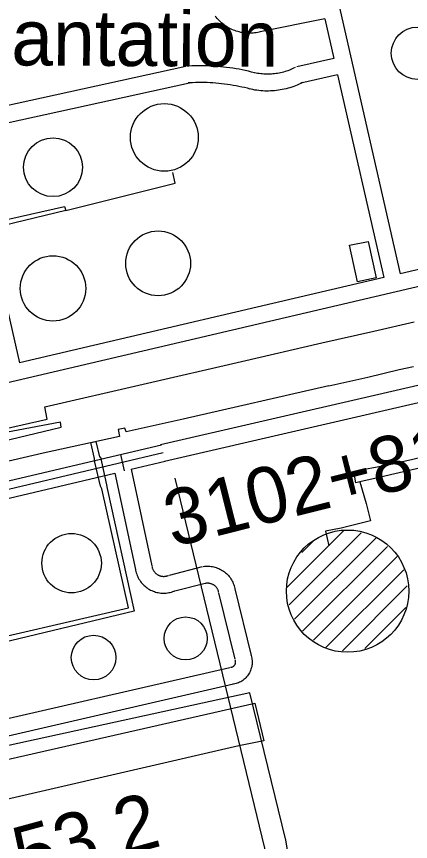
# Model space of a CAD drawing. Extents: x 3392644 to 3430565, y 576657 to 602123.
# Drawn here: x 3415681 to 3416383, y 584566 to 586038 of the extents above; entities that cross this region are included whole.
import ezdxf

# ---------------------------------------------------------------- set-up
doc = ezdxf.new("R2010")
doc.units = 0
for name, color, linetype in [('V-BLDG-IDEN', 7, 'Continuous'), ('V-BLDG-OTLN', 7, 'Continuous'), ('V-DOMW-TANK', 7, 'Continuous'), ('V-ROAD-CNTR', 7, 'Continuous'), ('V-SITE-OTLN', 7, 'Continuous'), ('V-SURV-IDEN', 7, 'Continuous'), ('V-TOPO-SHOR', 7, 'Continuous'), ('V-UTIL-LINE', 7, 'Continuous')]:
    doc.layers.add(name, color=color, linetype=linetype)

msp = doc.modelspace()

# ---------------------------------------------------------------- linework, layer by layer
at = {"layer": 'V-BLDG-OTLN'}
msp.add_lwpolyline([(3416308.1, 585636.6), (3416322, 585571.5), (3416288.7, 585564.4), (3416274.7, 585629.8)], close=True, dxfattribs=at)
at = {"layer": 'V-DOMW-TANK'}
for p, q in [((3416162.4, 585018.6), (3416264.3, 585120.5)), ((3416167.3, 584988.1), (3416295.7, 585116.5)), ((3416176.8, 584962.3), (3416322.9, 585108.3)), ((3416189.7, 585081.3), (3416210, 585101.5)), ((3416190.9, 584941), (3416342.2, 585092.3)), ((3416210.3, 584925), (3416359.8, 585074.5)), ((3416232.1, 584911.5), (3416371.3, 585050.7)), ((3416262.3, 584906.3), (3416377.7, 585021.8)), ((3416301.8, 584910.5), (3416374.9, 584983.6))]:
    msp.add_line(p, q, dxfattribs=at)
for centre, radius in [((3416395.9, 585972.7), 46.7), ((3415944.6, 585822.3), 60.4), ((3415746.2, 585769.1), 52.4), ((3415933.5, 585597.6), 57.8), ((3415746.1, 585552.9), 58.3), ((3416271.3, 585012.6), 109.1), ((3415779.3, 585062.5), 53), ((3415982.6, 584928.2), 38.4), ((3415818.5, 584894.1), 39.8)]:
    msp.add_circle(centre, radius, dxfattribs=at)
at = {"layer": 'V-ROAD-CNTR'}
msp.add_line((3415866.2, 585256.5), (3415873.1, 585227.3), dxfattribs=at)
for points in [[(3416145.1, 586545.8), (3416364.9, 585579.2)], [(3416116.1, 586010.9), (3416113.7, 586010.3), (3416111, 586009.8), (3416108.3, 586009.3), (3416105.6, 586008.9), (3416102.8, 586008.6), (3416100.1, 586008.4), (3416097.3, 586008.4), (3416094.6, 586008.4), (3416091.8, 586008.5), (3416089.1, 586008.7), (3416086.3, 586009), (3416083.6, 586009.4), (3416080.9, 586009.9), (3416078.2, 586010.6), (3416075.6, 586011.3), (3416072.9, 586012.1), (3416070.3, 586013), (3416067.8, 586014), (3416065.2, 586015), (3416062.7, 586016.2), (3416060.3, 586017.5), (3416057.9, 586018.8), (3416055.5, 586020.3), (3416053.3, 586021.8), (3416051, 586023.4), (3416048.8, 586025.1), (3416046.7, 586026.8), (3416044.7, 586028.7), (3416042.7, 586030.6), (3416040.8, 586032.6), (3416038.9, 586034.6), (3416037.2, 586036.7), (3416035.5, 586038.9)], [(3416230.7, 586034), (3416115.4, 586010.8)], [(3416230.7, 586034), (3416246.8, 585963.2)], [(3416246.8, 585963.2), (3416181, 585948.3)], [(3415448.7, 585832.1), (3415983.1, 585949.3)], [(3416105.3, 585937.7), (3416099.9, 585939.1), (3416094.4, 585940.4), (3416089, 585941.6), (3416083.4, 585942.8), (3416077.9, 585943.9), (3416072.4, 585944.8), (3416066.8, 585945.8), (3416061.2, 585946.6), (3416055.7, 585947.3), (3416050.1, 585948), (3416044.5, 585948.6), (3416038.9, 585949.1), (3416033.2, 585949.5), (3416027.6, 585949.8), (3416022, 585950), (3416016.4, 585950.2), (3416010.7, 585950.3), (3416005.1, 585950.3), (3415999.5, 585950.2), (3415993.8, 585950), (3415988.2, 585949.8), (3415985.5, 585949.6)], [(3416177.7, 585947.1), (3416175.1, 585945.8), (3416172.6, 585944.6), (3416170.1, 585943.5), (3416167.5, 585942.5), (3416165, 585941.5), (3416162.4, 585940.6), (3416159.8, 585939.8), (3416157.1, 585939), (3416154.5, 585938.3), (3416151.8, 585937.7), (3416149.1, 585937.1), (3416146.4, 585936.7), (3416143.7, 585936.2), (3416141, 585935.9), (3416138.3, 585935.6), (3416135.5, 585935.4), (3416132.8, 585935.2), (3416130.1, 585935.2), (3416127.3, 585935.2), (3416124.6, 585935.2), (3416121.8, 585935.4), (3416119.1, 585935.6), (3416116.4, 585935.8), (3416113.7, 585936.2), (3416110.9, 585936.6), (3416108.2, 585937.1), (3416105.5, 585937.7), (3416104.8, 585937.8)], [(3416253.5, 585934), (3416187.7, 585919)], [(3416253.5, 585934), (3416335.7, 585572.4)], [(3415455.2, 585802.8), (3415989.5, 585920)], [(3416097.8, 585908.6), (3416092.7, 585910), (3416087.6, 585911.2), (3416082.6, 585912.3), (3416077.5, 585913.4), (3416072.4, 585914.4), (3416067.3, 585915.3), (3416062.2, 585916.1), (3416057.1, 585916.9), (3416051.9, 585917.6), (3416046.8, 585918.2), (3416041.6, 585918.7), (3416036.4, 585919.2), (3416031.3, 585919.5), (3416026.1, 585919.8), (3416020.9, 585920.1), (3416015.7, 585920.2), (3416010.5, 585920.3), (3416005.3, 585920.3), (3416000.2, 585920.2), (3415995, 585920), (3415989.8, 585919.8), (3415987.1, 585919.7)], [(3416191.1, 585920.2), (3416188.1, 585918.7), (3416184.9, 585917.3), (3416181.7, 585915.9), (3416178.4, 585914.5), (3416175.2, 585913.3), (3416171.8, 585912.2), (3416168.5, 585911.1), (3416165.1, 585910.1), (3416161.7, 585909.2), (3416158.3, 585908.4), (3416154.9, 585907.7), (3416151.4, 585907.1), (3416148, 585906.5), (3416144.5, 585906.1), (3416141, 585905.7), (3416137.5, 585905.4), (3416134, 585905.3), (3416130.5, 585905.2), (3416127, 585905.2), (3416123.5, 585905.2), (3416120, 585905.4), (3416116.5, 585905.7), (3416113, 585906), (3416109.5, 585906.5), (3416106, 585907), (3416102.6, 585907.6), (3416099.2, 585908.3), (3416098.3, 585908.5)], [(3417410.7, 585793.4), (3415040.3, 585238.2)], [(3416857.5, 585694.6), (3416364.9, 585579.2)], [(3417653.5, 585639.1), (3415944.7, 585244.2)], [(3417448.6, 585622.5), (3415938, 585273.5)], [(3415643.6, 585606.2), (3415686.3, 585420.3)], [(3416335.7, 585572.4), (3415686.3, 585420.3)], [(3414841.6, 585028.8), (3415009.8, 585064.2), (3415617.8, 585197.9), (3415939.4, 585273.8)], [(3415942.8, 585259.2), (3415621.1, 585183.3), (3415013, 585049.5), (3414844.7, 585014.1)], [(3415885.4, 585230.2), (3415946.2, 585244.6)], [(3415483.8, 585137.7), (3415624.5, 585168.7), (3415856.2, 585223.3)], [(3415856.2, 585223.3), (3415893.1, 585051.3)], [(3415885.3, 585230.5), (3415885.6, 585229.3)], [(3415885.4, 585230.2), (3415922.4, 585057.6)], [(3415893, 585051.8), (3415893.4, 585049.8), (3415893.9, 585047.4), (3415894.5, 585045.1), (3415895.3, 585042.8), (3415896.2, 585040.6), (3415897.1, 585038.4), (3415898.2, 585036.2), (3415899.4, 585034.1), (3415900.7, 585032.1), (3415902, 585030.1), (3415903.5, 585028.2), (3415905, 585026.4), (3415906.6, 585024.6), (3415908.4, 585022.9), (3415910.2, 585021.3), (3415912, 585019.8), (3415913.9, 585018.3), (3415915.9, 585017), (3415918, 585015.7), (3415920.1, 585014.6), (3415922.3, 585013.5), (3415924.5, 585012.6), (3415926.8, 585011.8), (3415929, 585011), (3415931.4, 585010.4), (3415933.7, 585009.9), (3415936.1, 585009.5), (3415938.5, 585009.2), (3415940.9, 585009), (3415943.3, 585009), (3415945.7, 585009), (3415948.1, 585009.2), (3415950.5, 585009.5), (3415952.9, 585009.9), (3415955.2, 585010.3), (3415957.5, 585011), (3415959.8, 585011.7), (3415962, 585012.5), (3415963.1, 585012.9)], [(3415922.5, 585057.2), (3415922.7, 585055.8), (3415923, 585054.9), (3415923.2, 585053.9), (3415923.5, 585053), (3415923.9, 585052), (3415924.3, 585051.1), (3415924.7, 585050.2), (3415925.2, 585049.4), (3415925.8, 585048.5), (3415926.3, 585047.7), (3415926.9, 585046.9), (3415927.6, 585046.2), (3415928.2, 585045.4), (3415928.9, 585044.7), (3415929.7, 585044.1), (3415930.5, 585043.4), (3415931.3, 585042.8), (3415932.1, 585042.3), (3415932.9, 585041.8), (3415933.8, 585041.3), (3415934.7, 585040.9), (3415935.6, 585040.5), (3415936.5, 585040.1), (3415937.5, 585039.8), (3415938.4, 585039.6), (3415939.4, 585039.4), (3415940.4, 585039.2), (3415941.4, 585039.1), (3415942.4, 585039), (3415943.4, 585039), (3415944.4, 585039), (3415945.4, 585039.1), (3415946.3, 585039.2), (3415947.3, 585039.3), (3415948.3, 585039.6), (3415949.3, 585039.8), (3415950.2, 585040.1), (3415951.2, 585040.5), (3415951.8, 585040.7)], [(3415953.8, 585041.4), (3416012.4, 585056.3)], [(3416014, 585056.6), (3416016.1, 585056.9), (3416018.4, 585057.1), (3416020.8, 585057.2), (3416023.2, 585057.2), (3416025.6, 585057.1), (3416027.9, 585056.8), (3416030.3, 585056.5), (3416032.6, 585056), (3416034.9, 585055.4), (3416037.2, 585054.7), (3416039.5, 585053.9), (3416041.7, 585053), (3416043.8, 585052), (3416045.9, 585050.9), (3416048, 585049.6), (3416050, 585048.3), (3416051.9, 585046.9), (3416053.8, 585045.4), (3416055.5, 585043.8), (3416057.2, 585042.2), (3416058.8, 585040.4), (3416060.4, 585038.6), (3416061.8, 585036.7), (3416063.2, 585034.7), (3416064.4, 585032.7), (3416065.6, 585030.6), (3416066.6, 585028.4), (3416067.6, 585026.3), (3416068.4, 585024), (3416069.1, 585021.8), (3416069.8, 585019.5), (3416070.3, 585017.2), (3416070.5, 585015.9)], [(3415961.2, 585012.3), (3416019.8, 585027.2)], [(3416018.1, 585026.9), (3416019.4, 585027.1), (3416020.4, 585027.2), (3416021.3, 585027.2), (3416022.3, 585027.2), (3416023.2, 585027.2), (3416024.1, 585027.1), (3416025, 585026.9), (3416026, 585026.7), (3416026.9, 585026.5), (3416027.8, 585026.2), (3416028.7, 585025.9), (3416029.5, 585025.5), (3416030.4, 585025.1), (3416031.2, 585024.7), (3416032, 585024.2), (3416032.8, 585023.7), (3416033.6, 585023.1), (3416034.3, 585022.6), (3416035, 585021.9), (3416035.7, 585021.3), (3416036.3, 585020.6), (3416036.9, 585019.9), (3416037.5, 585019.1), (3416038, 585018.3), (3416038.5, 585017.5), (3416039, 585016.7), (3416039.4, 585015.9), (3416039.8, 585015), (3416040.1, 585014.1), (3416040.4, 585013.2), (3416040.6, 585012.3), (3416040.8, 585011.3), (3416041, 585010.6)], [(3416070.3, 585016.8), (3416099.2, 584898)], [(3416041.2, 585009.7), (3416070, 584890.9)], [(3416098.8, 584899.2), (3416099.4, 584897.5), (3416100, 584895.3), (3416100.5, 584893.1), (3416100.8, 584890.9), (3416101.1, 584888.6), (3416101.2, 584886.4), (3416101.1, 584884.1), (3416101, 584881.9), (3416100.7, 584879.6), (3416100.3, 584877.4), (3416099.7, 584875.2), (3416099.1, 584873.1), (3416098.3, 584870.9), (3416097.4, 584868.9), (3416096.4, 584866.8), (3416095.2, 584864.9), (3416094, 584863), (3416092.7, 584861.2), (3416091.2, 584859.4), (3416089.7, 584857.8), (3416088, 584856.2), (3416086.3, 584854.8), (3416084.5, 584853.4), (3416082.6, 584852.1), (3416080.7, 584851), (3416078.7, 584850), (3416076.6, 584849), (3416074.5, 584848.2), (3416072.4, 584847.5), (3416070.2, 584847), (3416068, 584846.6), (3416066.8, 584846.4)], [(3416070.4, 584889.6), (3416070.7, 584888.6), (3416070.9, 584888.1), (3416071, 584887.6), (3416071.1, 584887), (3416071.1, 584886.5), (3416071.2, 584885.9), (3416071.1, 584885.4), (3416071.1, 584884.8), (3416071, 584884.3), (3416070.9, 584883.7), (3416070.8, 584883.2), (3416070.6, 584882.6), (3416070.5, 584882.1), (3416070.2, 584881.6), (3416070, 584881.1), (3416069.7, 584880.6), (3416069.4, 584880.2), (3416069.1, 584879.7), (3416068.7, 584879.3), (3416068.3, 584878.9), (3416067.9, 584878.5), (3416067.5, 584878.2), (3416067.1, 584877.8), (3416066.6, 584877.5), (3416066.1, 584877.2), (3416065.6, 584877), (3416065.1, 584876.8), (3416064.6, 584876.6), (3416064.1, 584876.4), (3416063.6, 584876.3), (3416062.9, 584876.1), (3416062.4, 584876.1)], [(3416061.2, 584875.8), (3415574.2, 584763.6)], [(3416068, 584846.6), (3415580.9, 584734.4)]]:
    msp.add_lwpolyline(points, dxfattribs=at)
at = {"layer": 'V-SITE-OTLN'}
msp.add_lwpolyline([(3416164.3, 584550.7), (3416161.1, 584568), (3416097, 584831.4), (3415528, 584706.7), (3415441.1, 585124.8), (3414885.8, 585003.9), (3414787.6, 585534.1), (3414674, 586142.1), (3414579.1, 586564.1), (3414488.4, 587013.5), (3414833, 587097.6), (3414846.4, 587100.5), (3414856, 587102.4), (3414865.5, 587103.9), (3415026.6, 587138), (3415544.3, 587252.4), (3415572.5, 587260.1), (3415594.5, 587264.5), (3415667.1, 587280.6), (3416201.5, 587400.8), (3417016.1, 587577.2)], dxfattribs=at)
at = {"layer": 'V-TOPO-SHOR'}
msp.add_lwpolyline([(3415085.2, 584609.3), (3415094.3, 584582.4), (3416106.1, 584812.9), (3416122.1, 584745.6), (3416077.2, 584736.4), (3415168.6, 584526.6), (3415139.4, 584535.4), (3414977.9, 584496.7), (3414971, 584532.6), (3414973.2, 584552.8), (3414975.4, 584573), (3414977.6, 584575.3)], dxfattribs=at)
at = {"layer": 'V-UTIL-LINE'}
for points in [[(3414748.9, 586207.2), (3414831.3, 585765), (3414934.3, 585199.3), (3414951, 585115), (3415354.5, 585207.7), (3415760.9, 585305.2), (3415759.7, 585314.1), (3415652.8, 585293.8), (3415634.4, 585364.5), (3415644.7, 585367.7), (3415659.8, 585302.5), (3415735.9, 585319.4), (3415731.5, 585341.4), (3416082.4, 585422.3), (3416225.2, 585455.5)], [(3415769, 585691.9), (3415964, 585740.7), (3415959.8, 585759.9)], [(3415644.7, 585671.7), (3415766.4, 585699.3), (3415769, 585691.9), (3415658.2, 585665.1)], [(3416225.2, 585455.5), (3416318.1, 585476.6), (3416390, 585493.1)], [(3416427.5, 585238.6), (3416322, 585214.4), (3416293, 585207.5), (3416286.2, 585205.9), (3416282.6, 585226.6), (3416339.8, 585237.3), (3416387.4, 585248), (3416421.1, 585256.5), (3416418.3, 585265.5), (3416468.6, 585276.1), (3416550.7, 585293.3), (3416567.9, 585296.8), (3416564.4, 585307.2), (3416629.2, 585323.5), (3416741.5, 585349.8), (3416796, 585362.5), (3416883.5, 585383.1), (3416984.2, 585403.8), (3417053.9, 585416), (3417144.2, 585433.2), (3417204.8, 585447.4), (3417229, 585453.8), (3417231.8, 585443.5)], [(3416238, 585378.8), (3416307.3, 585394.7), (3416363.5, 585408.2), (3416388.5, 585413.7)], [(3416238, 585378.8), (3415977.9, 585319.3), (3415876.3, 585296.8), (3415874.4, 585303.7), (3415862.1, 585301.2), (3415864.5, 585288.8), (3415728.7, 585258.9), (3415432.9, 585189.8), (3414940.8, 585077.8), (3414887.3, 585065.2)], [(3415822.5, 585279.6), (3415829.1, 585252.5), (3415830.9, 585251.6), (3415841.7, 585202.2), (3415842.5, 585195.8), (3415890.8, 584977.1), (3415570.4, 584899.9), (3415567, 584910), (3415880.9, 584982.8), (3415833.4, 585195.1), (3415830.8, 585199.7), (3415820.7, 585242.7), (3415819.9, 585249.1), (3415813.4, 585277.6), (3415822.5, 585279.6)], [(3412089.9, 582100), (3412531, 582457.8), (3414603.6, 584199.2), (3415068.6, 584289.5), (3415163.5, 584253.5), (3416142.9, 584475.3), (3415963.7, 585214)], [(3416293, 585207.5), (3416304.2, 585168.9), (3416312.1, 585137.9), (3416259.7, 585125.1), (3416232.1, 585119.4), (3416237.8, 585093.2)]]:
    msp.add_lwpolyline(points, dxfattribs=at)

# ---------------------------------------------------------------- texts
at = {"layer": 'V-BLDG-IDEN'}
msp.add_text('Plantation', height=100, rotation=359.6858, dxfattribs=at).set_placement((3415552.7, 585951.6))
at = {"layer": 'V-SURV-IDEN'}
for s, rotation, p in [('3102+81.8', 14.1506, (3415959.3, 585090.6)), ('3108+53.2', 15.2822, (3415329.3, 584391.4))]:
    msp.add_text(s, height=100, rotation=rotation, dxfattribs=at).set_placement(p)

doc.saveas('drawing.dxf')
